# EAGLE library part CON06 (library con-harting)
CONNECTOR
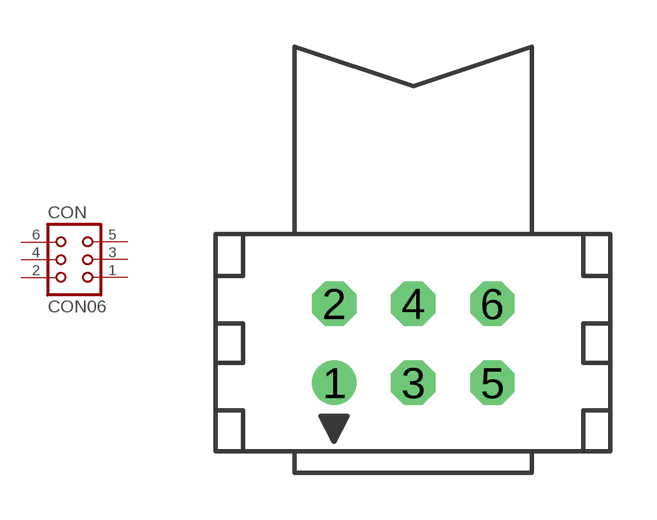
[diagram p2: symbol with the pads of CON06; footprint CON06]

Designator prefix CON

## CON06 (OC_FARNELL: unknown; OC_NEWARK: unknown)  [CON06]
1  1  pas
2  2  pas
3  3  pas
4  4  pas
5  5  pas
6  6  pas

## Footprint CON06 (pad centres in mm)
CONNECTOR
drill 0.914 round: 1 -2.54,-1.27
drill 0.914 octagon: 2 -2.54,1.27; 3 0,-1.27; 4 0,1.27; 5 2.54,-1.27; 6 2.54,1.27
